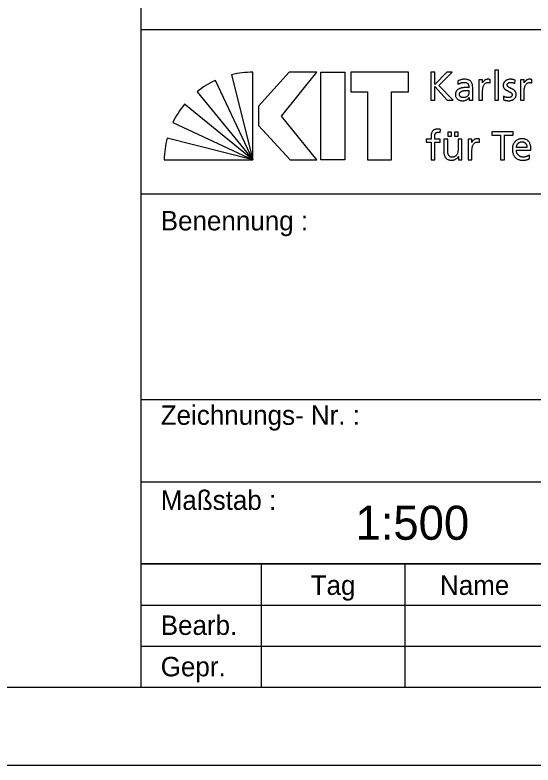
# Model space of a CAD drawing. Extents: x 0 to 210, y 0 to 148.
# Drawn here: x 157.5 to 184.16, y 0 to 38.58 of the extents above; entities that cross this region are included whole.
import ezdxf

# ---------------------------------------------------------------- set-up
doc = ezdxf.new("R2010")
doc.units = 0
doc.layers.add('90_Plankopf', color=7, linetype='Continuous')

msp = doc.modelspace()

# ---------------------------------------------------------------- linework, layer by layer
at = {"layer": '90_Plankopf'}
for p, q in [((164.001, 37.84), (164.001, 44.185)), ((164.001, 37.84), (206.001, 37.84)), ((168.638, 35.511), (169.741, 31.138)), ((169.741, 31.138), (169.741, 35.637)), ((178.905, 35.638), (178.905, 34.198)), ((169.741, 31.138), (167.817, 35.221)), ((180.29, 35.176), (180.3, 35.011)), ((181.964, 35.087), (181.964, 35.261)), ((183.229, 35.065), (183.245, 35.234)), ((184.106, 35.087), (184.106, 35.261)), ((181.06, 34.404), (181.06, 34.84)), ((166.872, 34.638), (169.741, 31.138)), ((180.866, 34.699), (180.866, 34.606)), ((182.649, 34.404), (182.639, 34.231)), ((169.741, 31.138), (166.217, 33.988)), ((178.905, 34.198), (179.112, 34.198)), ((179.753, 34.198), (180.055, 34.198)), ((165.62, 33.052), (169.741, 31.138)), ((179.387, 32.541), (179.395, 32.698)), ((169.741, 31.138), (165.329, 32.239)), ((181.414, 32.027), (181.414, 32.201)), ((183.854, 31.765), (183.309, 31.765)), ((183.309, 31.621), (184.06, 31.621)), ((183.979, 31.182), (183.979, 31.375)), ((165.183, 31.138), (169.741, 31.138)), ((164.001, 29.38), (206.001, 29.38)), ((164.001, 18.805), (206.001, 18.805)), ((164.001, 14.575), (206.001, 14.575)), ((164.001, 10.345), (206.001, 10.345)), ((164.001, 10.345), (206.001, 10.345)), ((164.001, 10.345), (206.001, 10.345)), ((164.001, 10.345), (206.001, 10.345)), ((164.001, 4), (164.001, 10.345)), ((170.177, 10.345), (170.177, 4)), ((177.589, 4), (177.589, 10.345)), ((164.001, 8.23), (185.001, 8.23)), ((164.001, 6.115), (185.001, 6.115)), ((164.001, 4), (206.001, 4)), ((164.001, 4), (206, 4))]:
    msp.add_line(p, q, dxfattribs=at)
for points in [[(0, 0), (210, 0), (210, 148.5), (0, 148.5)], [(4, 4), (206, 4), (206, 144.5), (4, 144.5)], [(173.034, 35.638), (171.619, 35.638), (170.037, 33.894), (170.037, 32.891), (171.669, 31.138), (173.043, 31.138), (171.212, 33.376)], [(174.486, 35.638), (174.486, 31.138), (173.251, 31.138), (173.251, 35.638)], [(174.782, 35.638), (174.782, 34.625), (175.651, 34.625), (175.651, 31.138), (176.886, 31.138), (176.886, 34.625), (177.755, 34.625), (177.755, 35.638)]]:
    msp.add_lwpolyline(points, close=True, dxfattribs=at)
for points in [[(164.001, 10.345), (164.001, 37.84)], [(180.055, 34.198), (179.324, 34.957), (180.001, 35.638), (179.726, 35.638), (179.112, 35.005), (179.112, 35.638), (178.905, 35.638)], [(182.191, 34.198), (182.385, 34.198), (182.385, 35.745), (182.191, 35.745), (182.191, 34.198)], [(181.561, 35.087), (181.557, 35.087), (181.557, 35.25), (181.376, 35.25), (181.376, 34.198), (181.57, 34.198), (181.57, 34.677)], [(183.704, 35.087), (183.7, 35.087), (183.7, 35.25), (183.518, 35.25), (183.518, 34.198), (183.712, 34.198), (183.712, 34.677)], [(179.112, 34.198), (179.112, 34.904), (179.753, 34.198)], [(180.882, 34.334), (180.886, 34.334), (180.886, 34.198), (181.068, 34.198)], [(179.778, 32.558), (179.778, 32.351), (179.972, 32.351), (179.972, 32.558), (179.778, 32.558)], [(180.116, 32.558), (180.116, 32.351), (180.31, 32.351), (180.31, 32.558), (180.116, 32.558)], [(182.496, 31.138), (182.702, 31.138), (182.702, 32.397), (183.15, 32.397), (183.15, 32.578), (182.048, 32.578), (182.048, 32.397), (182.496, 32.397), (182.496, 31.138)], [(178.913, 32.288), (178.913, 32.191), (178.665, 32.191), (178.665, 32.034), (178.913, 32.034), (178.913, 31.138), (179.107, 31.138), (179.107, 32.034), (179.385, 32.034), (179.385, 32.191), (179.107, 32.191), (179.107, 32.304)], [(179.771, 31.646), (179.771, 32.191), (179.577, 32.191), (179.577, 31.565)], [(180.508, 31.138), (180.508, 32.191), (180.314, 32.191), (180.314, 31.704)], [(181.012, 32.027), (181.008, 32.027), (181.008, 32.191), (180.826, 32.191), (180.826, 31.138), (181.02, 31.138), (181.02, 31.617)], [(180.316, 31.305), (180.32, 31.305), (180.32, 31.138), (180.508, 31.138)], [(206.001, 10.345), (164.001, 10.345)], [(164.001, 10.345), (164.001, 10.345)], [(164.001, 4), (206.001, 4)]]:
    msp.add_lwpolyline(points, dxfattribs=at)
for centre, start, end in [((169.725, 30.873), 89.8053, 103.1895), ((169.831, 30.904), 115.0126, 128.3968), ((169.909, 30.976), 140.7898, 154.174), ((169.946, 31.064), 165.7222, 179.1064)]:
    msp.add_arc(centre, 4.764, start, end, dxfattribs=at)
for points in [[(181.06, 34.84), (181.06, 34.935), (181.046, 35.015), (181.017, 35.08), (180.988, 35.145), (180.942, 35.193), (180.88, 35.226), (180.818, 35.258), (180.737, 35.275), (180.637, 35.275), (180.57, 35.275), (180.507, 35.265), (180.449, 35.247), (180.391, 35.229), (180.338, 35.206), (180.29, 35.176)], [(180.3, 35.011), (180.327, 35.033), (180.357, 35.052), (180.39, 35.068), (180.423, 35.084), (180.459, 35.096), (180.495, 35.105), (180.532, 35.114), (180.569, 35.118), (180.606, 35.118), (180.67, 35.118), (180.721, 35.108), (180.759, 35.088), (180.798, 35.067), (180.825, 35.036), (180.841, 34.996), (180.858, 34.955), (180.866, 34.904), (180.866, 34.844)], [(181.964, 35.261), (181.95, 35.263), (181.937, 35.266), (181.925, 35.268), (181.913, 35.27), (181.899, 35.272), (181.885, 35.273), (181.871, 35.274), (181.855, 35.275), (181.836, 35.275), (181.798, 35.275), (181.762, 35.267), (181.726, 35.251), (181.691, 35.235), (181.659, 35.213), (181.631, 35.184), (181.602, 35.156), (181.579, 35.124), (181.561, 35.087)], [(183.245, 35.234), (183.208, 35.245), (183.169, 35.255), (183.13, 35.263), (183.091, 35.271), (183.049, 35.275), (183.004, 35.275), (182.952, 35.275), (182.903, 35.268), (182.858, 35.255), (182.813, 35.242), (182.774, 35.222), (182.74, 35.195), (182.707, 35.168), (182.68, 35.135), (182.661, 35.094), (182.643, 35.053), (182.633, 35.006), (182.633, 34.951), (182.633, 34.909), (182.642, 34.873), (182.658, 34.842), (182.674, 34.811), (182.696, 34.785), (182.723, 34.762), (182.75, 34.74), (182.78, 34.72), (182.812, 34.702), (182.844, 34.685), (182.877, 34.669), (182.909, 34.654), (182.942, 34.638), (182.971, 34.622), (182.998, 34.606), (183.025, 34.59), (183.047, 34.572), (183.064, 34.551), (183.08, 34.531), (183.088, 34.508), (183.089, 34.481), (183.088, 34.452), (183.082, 34.429), (183.07, 34.409), (183.058, 34.39), (183.043, 34.374), (183.023, 34.363), (183.003, 34.351), (182.982, 34.343), (182.959, 34.338), (182.936, 34.332), (182.913, 34.33), (182.891, 34.33), (182.871, 34.33), (182.848, 34.333), (182.82, 34.338), (182.792, 34.344), (182.763, 34.352), (182.733, 34.363), (182.703, 34.374), (182.675, 34.388), (182.649, 34.404)], [(182.639, 34.231), (182.684, 34.208), (182.73, 34.192), (182.779, 34.184), (182.828, 34.176), (182.878, 34.172), (182.928, 34.173), (182.975, 34.173), (183.021, 34.18), (183.064, 34.193), (183.108, 34.206), (183.147, 34.226), (183.182, 34.253), (183.216, 34.28), (183.244, 34.314), (183.264, 34.355), (183.284, 34.396), (183.295, 34.445), (183.295, 34.501), (183.295, 34.549), (183.286, 34.59), (183.27, 34.623), (183.253, 34.656), (183.232, 34.685), (183.205, 34.708), (183.178, 34.731), (183.148, 34.751), (183.115, 34.767), (183.083, 34.784), (183.051, 34.799), (183.018, 34.813), (182.986, 34.828), (182.956, 34.843), (182.929, 34.858), (182.902, 34.874), (182.881, 34.892), (182.864, 34.913), (182.848, 34.934), (182.839, 34.96), (182.839, 34.99), (182.839, 35.019), (182.848, 35.043), (182.865, 35.062), (182.882, 35.081), (182.905, 35.095), (182.933, 35.104), (182.96, 35.114), (182.991, 35.118), (183.025, 35.118), (183.036, 35.118), (183.052, 35.116), (183.07, 35.114), (183.088, 35.111), (183.107, 35.106), (183.128, 35.101), (183.148, 35.096), (183.167, 35.091), (183.185, 35.084), (183.203, 35.078), (183.218, 35.071), (183.229, 35.065)], [(184.106, 35.261), (184.093, 35.263), (184.08, 35.266), (184.068, 35.268), (184.055, 35.27), (184.042, 35.272), (184.028, 35.273), (184.014, 35.274), (183.997, 35.275), (183.978, 35.275), (183.941, 35.275), (183.904, 35.267), (183.869, 35.251), (183.834, 35.235), (183.802, 35.213), (183.773, 35.184), (183.744, 35.156), (183.721, 35.124), (183.704, 35.087)], [(180.866, 34.844), (180.841, 34.845), (180.817, 34.846), (180.795, 34.846), (180.773, 34.847), (180.752, 34.848), (180.73, 34.848), (180.708, 34.848), (180.685, 34.848), (180.659, 34.848), (180.619, 34.848), (180.576, 34.844), (180.532, 34.837), (180.487, 34.83), (180.443, 34.818), (180.401, 34.802), (180.358, 34.786), (180.32, 34.764), (180.285, 34.737), (180.25, 34.711), (180.223, 34.678), (180.202, 34.639), (180.181, 34.6), (180.171, 34.554), (180.17, 34.501), (180.171, 34.425), (180.188, 34.363), (180.22, 34.314), (180.253, 34.266), (180.298, 34.23), (180.355, 34.207), (180.413, 34.184), (180.48, 34.173), (180.556, 34.173), (180.601, 34.173), (180.64, 34.179), (180.676, 34.189), (180.711, 34.2), (180.742, 34.213), (180.769, 34.229), (180.796, 34.246), (180.818, 34.264), (180.837, 34.282), (180.856, 34.3), (180.871, 34.317), (180.882, 34.334)], [(181.57, 34.677), (181.57, 34.765), (181.582, 34.841), (181.605, 34.905), (181.629, 34.969), (181.662, 35.019), (181.705, 35.053), (181.748, 35.088), (181.798, 35.105), (181.856, 35.106), (181.873, 35.106), (181.891, 35.105), (181.909, 35.102), (181.928, 35.099), (181.946, 35.094), (181.964, 35.087)], [(183.712, 34.677), (183.712, 34.765), (183.724, 34.841), (183.748, 34.905), (183.772, 34.969), (183.805, 35.019), (183.847, 35.053), (183.89, 35.088), (183.941, 35.105), (183.999, 35.106), (184.016, 35.106), (184.033, 35.105), (184.052, 35.102), (184.07, 35.099), (184.088, 35.094), (184.106, 35.087)], [(180.866, 34.606), (180.866, 34.554), (180.855, 34.506), (180.832, 34.465), (180.81, 34.423), (180.777, 34.391), (180.734, 34.367), (180.691, 34.343), (180.637, 34.33), (180.573, 34.33), (180.55, 34.33), (180.528, 34.334), (180.505, 34.341), (180.482, 34.348), (180.461, 34.359), (180.441, 34.374), (180.422, 34.388), (180.407, 34.406), (180.395, 34.427), (180.383, 34.449), (180.377, 34.473), (180.377, 34.501), (180.377, 34.538), (180.387, 34.569), (180.405, 34.594), (180.422, 34.618), (180.446, 34.638), (180.475, 34.652), (180.504, 34.667), (180.535, 34.678), (180.568, 34.686), (180.601, 34.693), (180.633, 34.698), (180.664, 34.7), (180.694, 34.703), (180.72, 34.704), (180.742, 34.703), (180.762, 34.703), (180.783, 34.703), (180.804, 34.701), (180.824, 34.7), (180.845, 34.7), (180.866, 34.699)], [(181.068, 34.198), (181.066, 34.208), (181.065, 34.222), (181.064, 34.238), (181.063, 34.256), (181.062, 34.278), (181.061, 34.305), (181.06, 34.331), (181.06, 34.365), (181.06, 34.404)], [(179.395, 32.698), (179.376, 32.701), (179.356, 32.704), (179.334, 32.707), (179.313, 32.709), (179.29, 32.711), (179.265, 32.711), (179.194, 32.71), (179.136, 32.7), (179.089, 32.681), (179.043, 32.661), (179.007, 32.632), (178.982, 32.595), (178.956, 32.558), (178.938, 32.513), (178.928, 32.461), (178.917, 32.41), (178.912, 32.352), (178.913, 32.288)], [(179.107, 32.304), (179.106, 32.34), (179.108, 32.373), (179.112, 32.403), (179.117, 32.433), (179.125, 32.46), (179.138, 32.482), (179.151, 32.505), (179.17, 32.522), (179.195, 32.535), (179.22, 32.547), (179.253, 32.554), (179.294, 32.554), (179.311, 32.554), (179.328, 32.553), (179.345, 32.551), (179.361, 32.548), (179.376, 32.545), (179.387, 32.541)], [(181.414, 32.201), (181.401, 32.204), (181.387, 32.206), (181.376, 32.208), (181.363, 32.21), (181.35, 32.212), (181.335, 32.213), (181.322, 32.215), (181.305, 32.215), (181.286, 32.215), (181.249, 32.215), (181.212, 32.207), (181.177, 32.191), (181.142, 32.175), (181.11, 32.153), (181.081, 32.125), (181.052, 32.097), (181.029, 32.064), (181.012, 32.027)], [(181.02, 31.617), (181.02, 31.705), (181.032, 31.782), (181.056, 31.846), (181.079, 31.91), (181.112, 31.959), (181.155, 31.993), (181.198, 32.028), (181.249, 32.046), (181.307, 32.046), (181.324, 32.046), (181.341, 32.045), (181.36, 32.042), (181.378, 32.04), (181.396, 32.035), (181.414, 32.027)], [(184.06, 31.621), (184.06, 31.706), (184.052, 31.785), (184.037, 31.857), (184.021, 31.929), (183.995, 31.991), (183.959, 32.045), (183.923, 32.099), (183.876, 32.14), (183.816, 32.17), (183.756, 32.2), (183.683, 32.215), (183.595, 32.215), (183.521, 32.215), (183.453, 32.202), (183.393, 32.176), (183.333, 32.15), (183.281, 32.114), (183.237, 32.066), (183.194, 32.019), (183.161, 31.963), (183.138, 31.897), (183.114, 31.833), (183.103, 31.761), (183.102, 31.683), (183.102, 31.597), (183.113, 31.519), (183.135, 31.449), (183.157, 31.38), (183.19, 31.32), (183.235, 31.27), (183.279, 31.22), (183.336, 31.181), (183.404, 31.154), (183.473, 31.127), (183.554, 31.114), (183.647, 31.113), (183.704, 31.114), (183.753, 31.118), (183.794, 31.125), (183.834, 31.133), (183.869, 31.142), (183.899, 31.152), (183.928, 31.162), (183.955, 31.172), (183.979, 31.182)], [(183.309, 31.765), (183.312, 31.8), (183.32, 31.834), (183.332, 31.869), (183.344, 31.903), (183.362, 31.934), (183.384, 31.963), (183.407, 31.992), (183.435, 32.015), (183.469, 32.032), (183.503, 32.049), (183.544, 32.058), (183.591, 32.058), (183.633, 32.058), (183.67, 32.051), (183.703, 32.035), (183.735, 32.02), (183.763, 31.999), (183.785, 31.972), (183.807, 31.946), (183.824, 31.914), (183.836, 31.879), (183.848, 31.844), (183.854, 31.806), (183.854, 31.765)], [(180.314, 31.704), (180.314, 31.639), (180.308, 31.581), (180.295, 31.528), (180.282, 31.475), (180.263, 31.429), (180.237, 31.391), (180.211, 31.352), (180.177, 31.323), (180.137, 31.302), (180.097, 31.281), (180.049, 31.271), (179.994, 31.27), (179.938, 31.274), (179.894, 31.289), (179.861, 31.318), (179.828, 31.346), (179.805, 31.387), (179.791, 31.442), (179.778, 31.496), (179.771, 31.564), (179.771, 31.646)], [(179.577, 31.565), (179.577, 31.471), (179.591, 31.39), (179.619, 31.323), (179.647, 31.255), (179.69, 31.204), (179.748, 31.168), (179.806, 31.132), (179.881, 31.114), (179.972, 31.113), (180.021, 31.114), (180.068, 31.121), (180.113, 31.136), (180.158, 31.152), (180.198, 31.174), (180.234, 31.202), (180.269, 31.231), (180.296, 31.265), (180.316, 31.305)], [(183.979, 31.375), (183.967, 31.366), (183.95, 31.355), (183.927, 31.342), (183.904, 31.33), (183.878, 31.319), (183.848, 31.308), (183.818, 31.297), (183.786, 31.288), (183.753, 31.281), (183.72, 31.274), (183.688, 31.271), (183.655, 31.27), (183.609, 31.271), (183.565, 31.279), (183.524, 31.296), (183.482, 31.313), (183.445, 31.337), (183.413, 31.368), (183.381, 31.399), (183.355, 31.435), (183.337, 31.478), (183.319, 31.521), (183.309, 31.569), (183.309, 31.621)]]:
    msp.add_open_spline(points, degree=3, dxfattribs=at)

# ---------------------------------------------------------------- texts
for s, height, p in [('Benennung :', 1, (165.001, 27.5)), ('Zeichnungs- Nr. :', 1, (165.001, 17.5)), ('Maßstab :', 1, (165.001, 13.125)), ('1:500   ', 1.75, (175.024, 11.587)), ('Tag', 1, (172.721, 8.75)), ('Name', 1, (179.376, 8.75)), ('Bearb.', 1, (165.001, 6.692)), ('Gepr.', 1, (165.001, 4.561))]:
    msp.add_text(s, height=height, dxfattribs=at).set_placement(p)

doc.saveas('drawing.dxf')
